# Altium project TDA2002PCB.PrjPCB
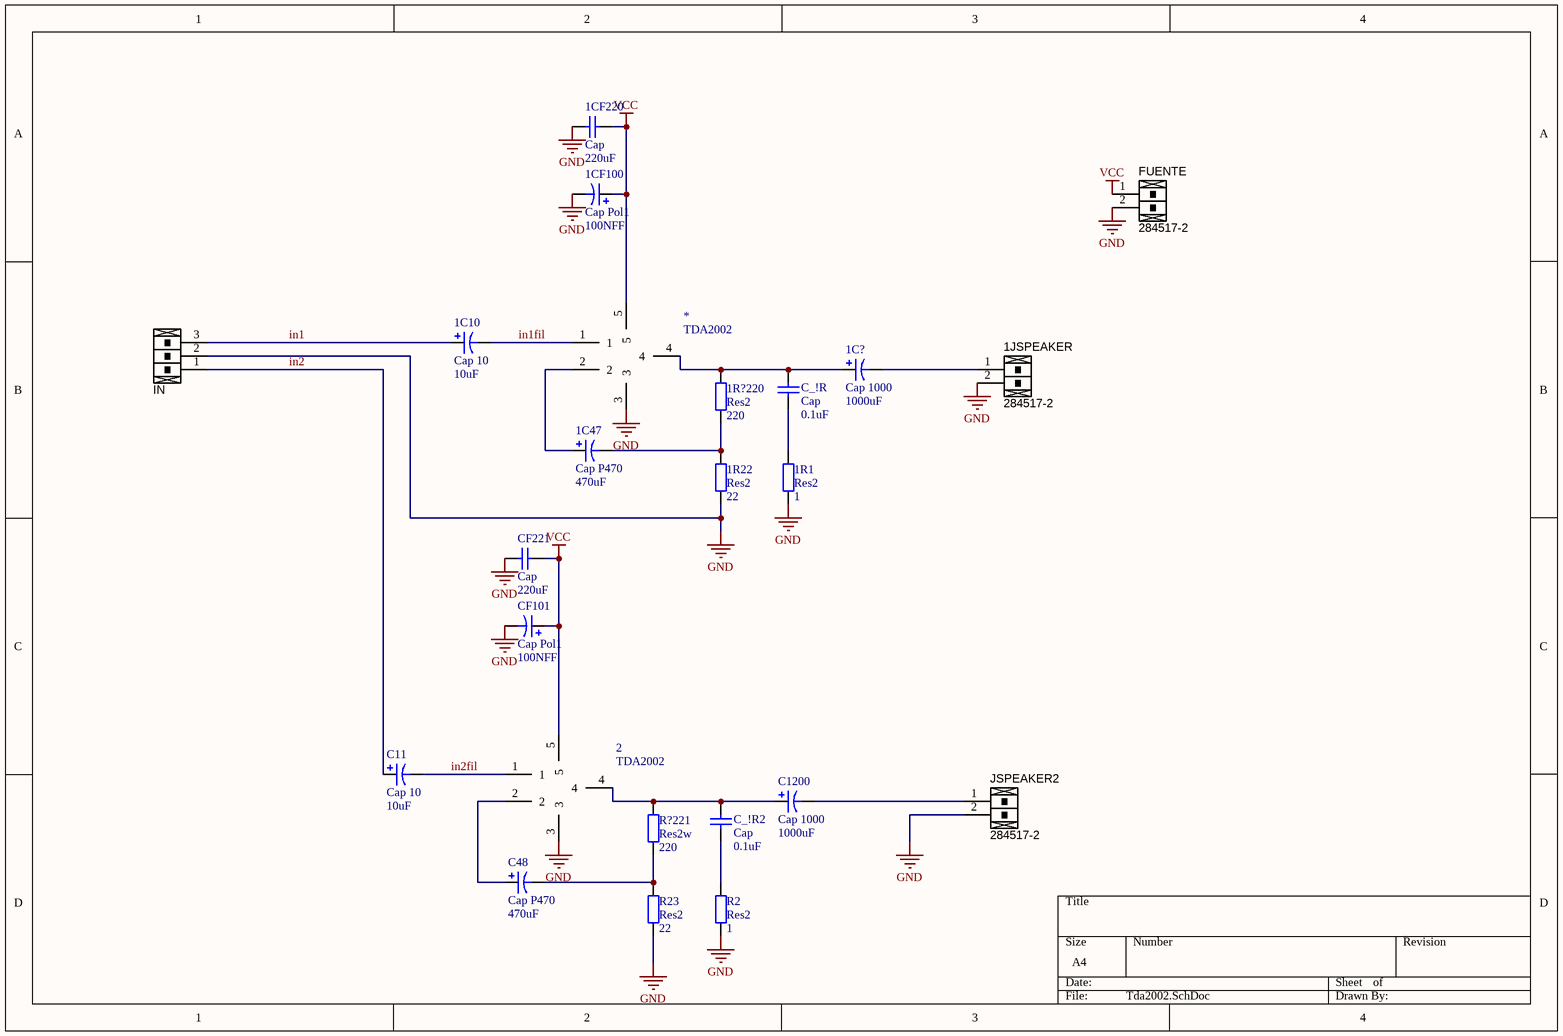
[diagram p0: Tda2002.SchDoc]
1 sheet, 24 parts. Net scope: global (net labels, ports and power ports of the same name join across sheets).
Board file: TDA.PcbDoc

## Sheet Tda2002.SchDoc
size A4

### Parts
1C10  Cap 10  value 10uF  [CAPPR5-5X7]
1C47  Cap P470  value 470uF  [cappr5-10x5]
1C?  Cap 1000  value 1000uF  [cappr5-10x5]
1CF100  Cap Pol1  value 100NFF  [CAPR5-4X5]
1CF220  Cap  value 220uF  [cappr2.5-6.3x7]
1JSPEAKER  Manufacturer Part Number 1: 284517-2  [PIN2]  (hidden comment: 2P_TERM_BLOCK_HEADER)
1R1  Res2  value 1  [RESTH_AXIAL-0.4]
1R22  Res2  value 22  [RESTH_AXIAL-0.4]
1R?220  Res2  value 220  [RESTH_AXIAL-0.4]
2  TDA2002  [PentawattV]
*  TDA2002  [PentawattV]
C11  Cap 10  value 10uF  [CAPPR5-5X7]
C48  Cap P470  value 470uF  [cappr5-10x5]
C1200  Cap 1000  value 1000uF  [cappr5-10x5]
C_!R  Cap  value 0.1uF  [CAPR5-4X5]
C_!R2  Cap  value 0.1uF  [CAPR5-4X5]
CF101  Cap Pol1  value 100NFF  [CAPR5-4X5]
CF221  Cap  value 220uF  [cappr2.5-6.3x7]
FUENTE  Manufacturer Part Number 1: 284517-2  [pin2]  (hidden comment: 2P_TERM_BLOCK_HEADER)
IN  3P_TERM BLOCK HEADER  [E3]  (value not drawn)
JSPEAKER2  Manufacturer Part Number 1: 284517-2  [pin2]  (hidden comment: 2P_TERM_BLOCK_HEADER)
R2  Res2  value 1  [RESTH_AXIAL-0.4]
R23  Res2  value 22  [RESTH_AXIAL-0.4]
R?221  Res2w  value 220  [RESTH_AXIAL-0.4]

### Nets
GND: 1CF100.2 1CF220.1 1JSPEAKER.2 1R1.2 1R22.1 2.3 *.3 CF101.2 CF221.1 FUENTE.2 IN.2 JSPEAKER2.2 R2.2 R23.1
VCC: 1CF100.1 1CF220.2 2.5 *.5 CF101.1 CF221.2 FUENTE.1
in1: 1C10.1 IN.3
in1fil: 1C10.2 *.1
in2: C11.1 IN.1
in2fil: 2.1 C11.2
Net1C47_1: 1C47.1 *.2
Net1C47_2: 1C47.2 1R22.2 1R?220.1
Net1C?_1: 1C?.1 1R?220.2 *.4 C_!R.2
Net1C?_2: 1C?.2 1JSPEAKER.1
Net1R1_1: 1R1.1 C_!R.1
Net2_2: 2.2 C48.1
Net2_4: 2.4 C1200.1 C_!R2.2 R?221.2
NetC48_2: C48.2 R23.2 R?221.1
NetC1200_2: C1200.2 JSPEAKER2.1
NetC_!R2_1: C_!R2.1 R2.1

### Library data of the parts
1C10 1C47 1C? 1CF100 C11 C48 C1200 CF101 = Cap Pol1: Polarized Capacitor (Radial)
1CF220 C_!R C_!R2 CF221 = Cap: Capacitor
1JSPEAKER FUENTE JSPEAKER2 = 2P_TERM_BLOCK_HEADER: Terminal Block THT 2-position header 3.81mm pitch; Manufacturer 1: TE Connectivity; Pitch: 0.150" (3.81mm); Voltage: 300V; Positions Per Level: 2; Mating Connector: 284507-2; SCDType: undef
1R1 1R22 1R?220 R2 R23 R?221 = Res2: Resistor
IN = 3P_TERM BLOCK HEADER: Terminal Block THT 3-Position header 3.81mm pitch; Manufacturer 1: TE Connectivity; Manufacturer Part Number 1: 284517-3; Pitch: 0.150" (3.81mm); Voltage: 300V; Mating Connector: 284507-3; Value: 3 position; Positions Per Level: 3; SCDType: undef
